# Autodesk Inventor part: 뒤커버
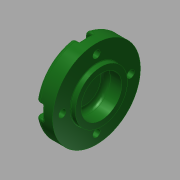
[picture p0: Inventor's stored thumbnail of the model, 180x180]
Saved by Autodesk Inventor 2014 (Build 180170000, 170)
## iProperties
Created: 2015-11
Part Number: 뒤커버
Material: 알루미늄 6061
Document SubType Name: Modeling
Designer: mduedu
Density: 1 g/cm^3
Appearance: 매끄러움 - 짙은 산림 녹색
Author: mduedu
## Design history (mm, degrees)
sketch "스케치1"
  geometry: L1 (-7, 0)-(7, 0); L2 (-7, 0)-(-7, 27); L3 (-7, 27)-(4, 27); L4 (4, 27)-(4, 16); L5 (4, 16)-(7, 16); L6 (7, 16)-(7, 0); 2 further points
  constraints: 12 end point, 3 perpendicular, 2 parallel, 1 coincident, 1 horizontal, 1 midpoint
  dimensions: "d0" = 14 distance of L1.start L1.end; "d1" = 54 diameter of L3 L1; "d2" = 3 distance of L4.end L5.end; "d3" = 32 diameter of L5 L1
revolve "회전1" sketch "스케치1" stored, may be unused: angle "d4" = 90 deg
hole "구멍1" diameter "d7" = 25; stored, may be unused: countersink angle "d11" = 90 deg, drill point angle "d13" = 0 deg; dims "d8" = 6, "d9" = 4, "d10" = 2, "d12" = 10, "d66" = 10, "d67" = 10
fillet "모깎기2" dims "d36" = 3
fillet "모깎기3" dims "d37" = 3
fillet "모깎기4" dims "d38" = 0.3
sketch "스케치3" dims "d61" = 42
  geometry: C1 r 27 at (0, 0) reference; 2 further points
  constraints: 2 vertical alignment, 1 coincident, 2 other
hole "구멍4" sketch "스케치3" at (0, 21) diameter "d44" = 4.5; stored, may be unused: countersink angle "d48" = 90 deg, drill point angle "d50" = 0 deg; dims "d45" = 6, "d46" = 8, "d47" = 4.6, "d49" = 8
sketch "스케치4"
  geometry: L1 (-4, 5.702)-(-4, 0); L2 (4, 5.702)-(4, 0); A1 r 27 centre (0, -21) between (-4, 5.702) and (4, 5.702) reference; A2 r 4 centre (0, 0) between (-2.824, 2.833) and (2.824, 2.833) reference
  constraints: 4 end point, 4 point on circle, 2 tangent, 2 vertical
extrude "돌출1" cut sketch "스케치4" stored distance "d51" = 0; taper "d52" = 0 deg
fillet "모깎기5" dims "d56" = 0.3
fillet "모깎기6" dims "d57" = 1
node "솔리드1"
pattern_circular "원형 패턴2" dims angle "d64" = 360 deg
pattern_circular "원형 패턴1" dims angle "d54" = 360 deg
